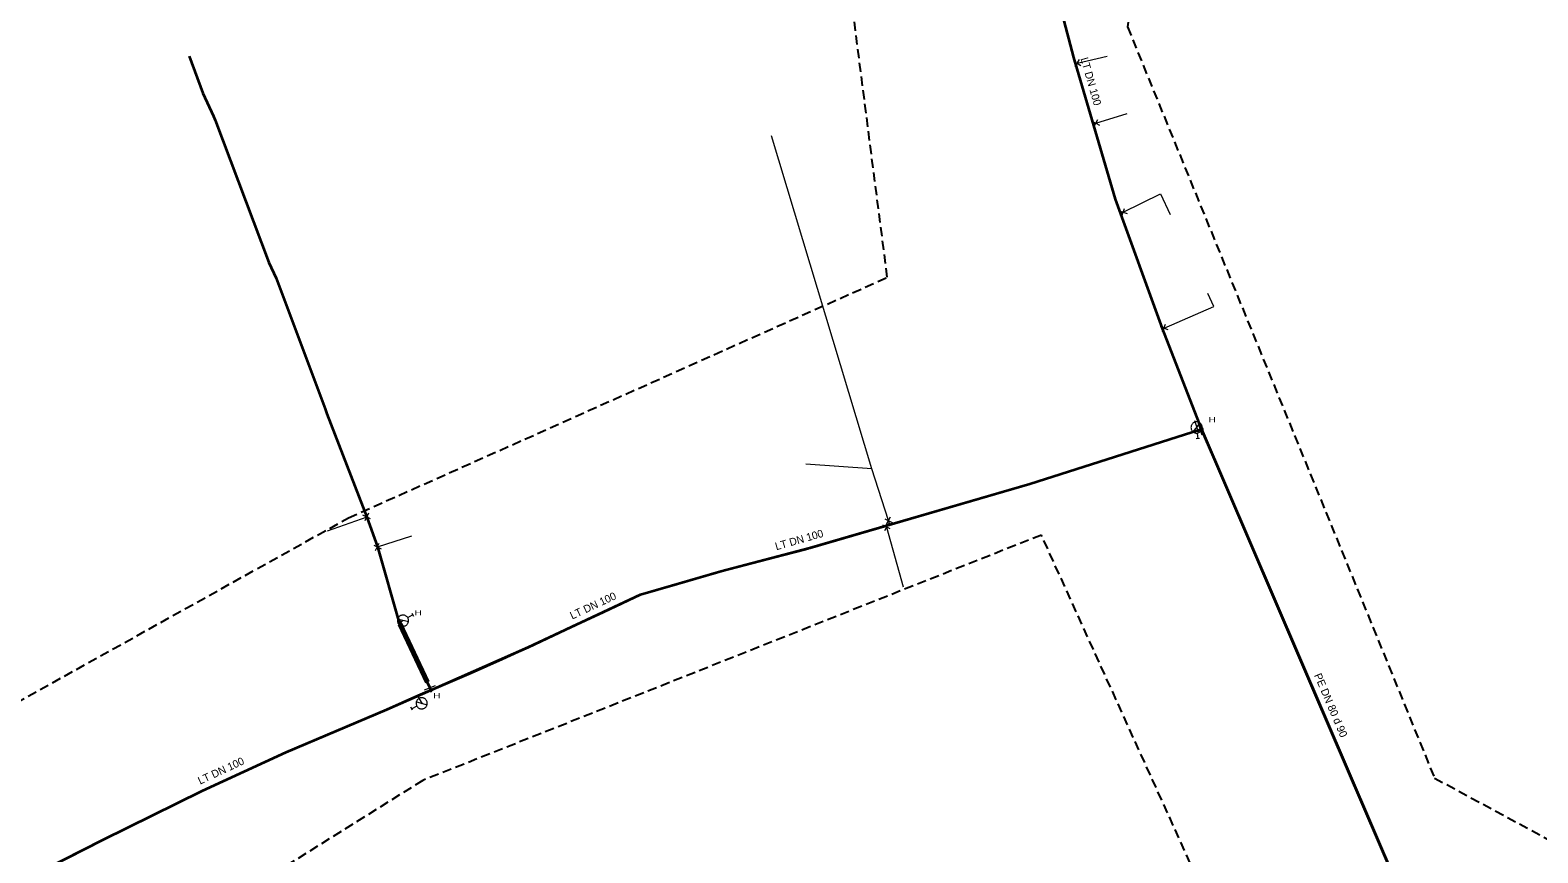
# Model space of a CAD drawing. Extents: x -743677 to -742923, y -1027084 to -1026416.
# Drawn here: x -743300.4 to -743064.4, y -1026690.3 to -1026561.5 of the extents above; entities that cross this region are included whole.
import ezdxf

# ---------------------------------------------------------------- set-up
doc = ezdxf.new("R2010")
doc.units = 0
doc.header["$LTSCALE"] = 0.48
doc.linetypes.add('MEDIUM_DASHED', pattern=[4.5, 3, -1.5])
for name, color, linetype, lineweight in [('15', 7, 'Continuous', 13), ('16', 7, 'Continuous', 35), ('20', 7, 'Continuous', 13), ('23', 7, 'Continuous', 70), ('59', 7, 'Continuous', 13), ('62', 7, 'MEDIUM_DASHED', 25)]:
    doc.layers.add(name, color=color, linetype=linetype, lineweight=lineweight)
doc.layers.add('17', color=7, linetype='Continuous')

msp = doc.modelspace()

# ---------------------------------------------------------------- linework, layer by layer
at = {"layer": '15'}
for p, q in [((-743137.057, -1026566.381), (-743135.96, -1026567.061)), ((-743136.85, -1026567.272), (-743136.167, -1026566.164)), ((-743134.177, -1026575.805), (-743133.041, -1026576.417)), ((-743133.916, -1026576.682), (-743133.301, -1026575.535)), ((-743129.919, -1026589.853), (-743128.698, -1026590.268)), ((-743129.517, -1026590.675), (-743129.101, -1026589.442)), ((-743123.518, -1026607.952), (-743122.319, -1026608.43)), ((-743123.159, -1026608.793), (-743122.679, -1026607.583)), ((-743118.136, -1026622.664), (-743117.563, -1026624.436)), ((-743116.971, -1026624.944), (-743117.548, -1026623.174)), ((-743247.117, -1026638.035), (-743248.283, -1026637.482)), ((-743247.422, -1026637.172), (-743247.978, -1026638.349)), ((-743166.615, -1026638.031), (-743165.462, -1026638.611)), ((-743166.33, -1026638.9), (-743165.747, -1026637.736)), ((-743165.777, -1026639.624), (-743166.924, -1026639.033)), ((-743166.053, -1026638.752), (-743166.647, -1026639.91)), ((-743246.601, -1026642.153), (-743245.456, -1026642.749)), ((-743246.328, -1026643.026), (-743245.729, -1026641.87)), ((-743241.867, -1026654.975), (-743242.832, -1026653.383)), ((-743238.664, -1026664.832), (-743236.934, -1026664.146))]:
    msp.add_line(p, q, dxfattribs=at)
for points in [[(-743116.803, -1026623.984), (-743116.809, -1026623.932), (-743116.826, -1026623.882), (-743116.855, -1026623.838), (-743116.892, -1026623.801), (-743116.937, -1026623.774), (-743116.987, -1026623.757), (-743117.04, -1026623.753), (-743117.092, -1026623.76), (-743117.141, -1026623.779), (-743117.184, -1026623.808), (-743117.22, -1026623.847), (-743117.246, -1026623.892), (-743117.262, -1026623.943), (-743117.265, -1026623.995), (-743117.257, -1026624.047), (-743117.237, -1026624.096), (-743117.206, -1026624.139), (-743117.167, -1026624.173), (-743117.121, -1026624.199), (-743117.07, -1026624.213), (-743117.017, -1026624.215), (-743116.966, -1026624.205), (-743116.918, -1026624.184), (-743116.875, -1026624.153), (-743116.841, -1026624.112), (-743116.817, -1026624.066), (-743116.804, -1026624.015)], [(-743116.833, -1026623.984), (-743116.839, -1026623.935), (-743116.856, -1026623.889), (-743116.884, -1026623.849), (-743116.921, -1026623.817), (-743116.965, -1026623.795), (-743117.013, -1026623.784), (-743117.062, -1026623.784), (-743117.108, -1026623.797), (-743117.152, -1026623.821), (-743117.188, -1026623.854), (-743117.215, -1026623.895), (-743117.231, -1026623.942), (-743117.235, -1026623.991), (-743117.228, -1026624.039), (-743117.209, -1026624.084), (-743117.179, -1026624.124), (-743117.141, -1026624.155), (-743117.097, -1026624.175), (-743117.049, -1026624.185), (-743117, -1026624.183), (-743116.953, -1026624.168), (-743116.91, -1026624.143), (-743116.875, -1026624.109), (-743116.85, -1026624.067), (-743116.836, -1026624.02)], [(-743116.863, -1026623.984), (-743116.869, -1026623.939), (-743116.886, -1026623.897), (-743116.914, -1026623.862), (-743116.95, -1026623.835), (-743116.992, -1026623.818), (-743117.037, -1026623.813), (-743117.081, -1026623.819), (-743117.123, -1026623.838), (-743117.157, -1026623.866), (-743117.184, -1026623.903), (-743117.201, -1026623.945), (-743117.205, -1026623.99), (-743117.198, -1026624.035), (-743117.179, -1026624.076), (-743117.15, -1026624.11), (-743117.113, -1026624.136), (-743117.07, -1026624.152), (-743117.025, -1026624.155), (-743116.98, -1026624.147), (-743116.94, -1026624.127), (-743116.906, -1026624.098), (-743116.88, -1026624.06), (-743116.866, -1026624.017)], [(-743116.893, -1026623.984), (-743116.897, -1026623.943), (-743116.916, -1026623.906), (-743116.943, -1026623.875), (-743116.978, -1026623.854), (-743117.018, -1026623.843), (-743117.059, -1026623.845), (-743117.098, -1026623.858), (-743117.132, -1026623.882), (-743117.157, -1026623.914), (-743117.172, -1026623.952), (-743117.174, -1026623.993), (-743117.167, -1026624.033), (-743117.147, -1026624.069), (-743117.118, -1026624.098), (-743117.081, -1026624.117), (-743117.041, -1026624.125), (-743117, -1026624.121), (-743116.962, -1026624.106), (-743116.929, -1026624.08), (-743116.907, -1026624.046), (-743116.894, -1026624.007)], [(-743116.923, -1026623.984), (-743116.928, -1026623.948), (-743116.946, -1026623.916), (-743116.972, -1026623.891), (-743117.005, -1026623.876), (-743117.042, -1026623.873), (-743117.076, -1026623.881), (-743117.108, -1026623.901), (-743117.13, -1026623.929), (-743117.144, -1026623.963), (-743117.144, -1026624), (-743117.133, -1026624.035), (-743117.112, -1026624.064), (-743117.081, -1026624.085), (-743117.047, -1026624.095), (-743117.01, -1026624.093), (-743116.976, -1026624.079), (-743116.949, -1026624.056), (-743116.929, -1026624.024), (-743116.923, -1026623.989)], [(-743116.953, -1026623.984), (-743116.958, -1026623.953), (-743116.975, -1026623.927), (-743117, -1026623.91), (-743117.031, -1026623.903), (-743117.062, -1026623.907), (-743117.089, -1026623.924), (-743117.107, -1026623.948), (-743117.115, -1026623.979), (-743117.111, -1026624.009), (-743117.096, -1026624.037), (-743117.071, -1026624.056), (-743117.042, -1026624.065), (-743117.011, -1026624.062), (-743116.983, -1026624.048), (-743116.963, -1026624.024), (-743116.953, -1026623.995)], [(-743116.983, -1026623.984), (-743116.988, -1026623.96), (-743117.005, -1026623.942), (-743117.027, -1026623.933), (-743117.052, -1026623.936), (-743117.073, -1026623.95), (-743117.084, -1026623.972), (-743117.084, -1026623.997), (-743117.071, -1026624.018), (-743117.052, -1026624.032), (-743117.027, -1026624.035), (-743117.004, -1026624.026), (-743116.988, -1026624.008)], [(-743117.013, -1026623.984), (-743117.018, -1026623.969), (-743117.032, -1026623.963), (-743117.048, -1026623.967), (-743117.054, -1026623.981), (-743117.051, -1026623.996), (-743117.038, -1026624.005), (-743117.022, -1026624.002), (-743117.013, -1026623.99)], [(-743237.449, -1026664.856), (-743237.455, -1026664.804), (-743237.472, -1026664.754), (-743237.501, -1026664.71), (-743237.538, -1026664.673), (-743237.583, -1026664.646), (-743237.633, -1026664.629), (-743237.686, -1026664.625), (-743237.738, -1026664.632), (-743237.787, -1026664.651), (-743237.83, -1026664.68), (-743237.866, -1026664.719), (-743237.892, -1026664.764), (-743237.908, -1026664.815), (-743237.911, -1026664.867), (-743237.903, -1026664.919), (-743237.883, -1026664.968), (-743237.852, -1026665.011), (-743237.813, -1026665.045), (-743237.767, -1026665.071), (-743237.716, -1026665.085), (-743237.663, -1026665.087), (-743237.612, -1026665.077), (-743237.564, -1026665.056), (-743237.521, -1026665.025), (-743237.487, -1026664.984), (-743237.463, -1026664.938), (-743237.451, -1026664.887)], [(-743237.479, -1026664.856), (-743237.485, -1026664.807), (-743237.502, -1026664.761), (-743237.53, -1026664.721), (-743237.567, -1026664.689), (-743237.611, -1026664.667), (-743237.659, -1026664.656), (-743237.708, -1026664.656), (-743237.755, -1026664.669), (-743237.798, -1026664.693), (-743237.834, -1026664.726), (-743237.861, -1026664.767), (-743237.877, -1026664.814), (-743237.881, -1026664.863), (-743237.874, -1026664.911), (-743237.855, -1026664.956), (-743237.825, -1026664.996), (-743237.787, -1026665.027), (-743237.743, -1026665.047), (-743237.695, -1026665.057), (-743237.646, -1026665.055), (-743237.599, -1026665.04), (-743237.556, -1026665.015), (-743237.522, -1026664.981), (-743237.496, -1026664.939), (-743237.482, -1026664.892)], [(-743237.509, -1026664.856), (-743237.515, -1026664.811), (-743237.532, -1026664.769), (-743237.56, -1026664.734), (-743237.596, -1026664.707), (-743237.638, -1026664.69), (-743237.683, -1026664.685), (-743237.728, -1026664.691), (-743237.769, -1026664.71), (-743237.804, -1026664.738), (-743237.831, -1026664.775), (-743237.847, -1026664.817), (-743237.851, -1026664.862), (-743237.844, -1026664.907), (-743237.825, -1026664.948), (-743237.796, -1026664.982), (-743237.759, -1026665.008), (-743237.716, -1026665.024), (-743237.671, -1026665.027), (-743237.626, -1026665.019), (-743237.586, -1026664.999), (-743237.552, -1026664.97), (-743237.526, -1026664.932), (-743237.512, -1026664.889)], [(-743237.539, -1026664.856), (-743237.544, -1026664.815), (-743237.562, -1026664.778), (-743237.589, -1026664.747), (-743237.624, -1026664.726), (-743237.664, -1026664.715), (-743237.705, -1026664.717), (-743237.744, -1026664.73), (-743237.778, -1026664.754), (-743237.803, -1026664.786), (-743237.818, -1026664.824), (-743237.821, -1026664.865), (-743237.813, -1026664.905), (-743237.793, -1026664.941), (-743237.764, -1026664.97), (-743237.727, -1026664.989), (-743237.687, -1026664.997), (-743237.646, -1026664.993), (-743237.608, -1026664.978), (-743237.576, -1026664.952), (-743237.553, -1026664.918), (-743237.54, -1026664.879)], [(-743237.569, -1026664.856), (-743237.574, -1026664.82), (-743237.592, -1026664.788), (-743237.618, -1026664.763), (-743237.652, -1026664.748), (-743237.688, -1026664.745), (-743237.723, -1026664.753), (-743237.754, -1026664.773), (-743237.777, -1026664.801), (-743237.79, -1026664.835), (-743237.79, -1026664.872), (-743237.779, -1026664.907), (-743237.758, -1026664.936), (-743237.728, -1026664.957), (-743237.693, -1026664.967), (-743237.656, -1026664.965), (-743237.622, -1026664.951), (-743237.595, -1026664.928), (-743237.576, -1026664.896), (-743237.569, -1026664.861)], [(-743237.599, -1026664.856), (-743237.604, -1026664.825), (-743237.621, -1026664.799), (-743237.647, -1026664.782), (-743237.677, -1026664.775), (-743237.708, -1026664.779), (-743237.735, -1026664.796), (-743237.753, -1026664.82), (-743237.761, -1026664.851), (-743237.757, -1026664.881), (-743237.742, -1026664.909), (-743237.718, -1026664.928), (-743237.688, -1026664.937), (-743237.657, -1026664.934), (-743237.629, -1026664.92), (-743237.609, -1026664.896), (-743237.599, -1026664.867)], [(-743237.629, -1026664.856), (-743237.634, -1026664.832), (-743237.651, -1026664.814), (-743237.674, -1026664.805), (-743237.698, -1026664.808), (-743237.719, -1026664.822), (-743237.73, -1026664.844), (-743237.73, -1026664.869), (-743237.718, -1026664.89), (-743237.698, -1026664.904), (-743237.673, -1026664.907), (-743237.65, -1026664.898), (-743237.634, -1026664.88)], [(-743237.659, -1026664.856), (-743237.664, -1026664.841), (-743237.679, -1026664.835), (-743237.694, -1026664.839), (-743237.701, -1026664.853), (-743237.697, -1026664.868), (-743237.684, -1026664.877), (-743237.669, -1026664.874), (-743237.659, -1026664.862)]]:
    msp.add_lwpolyline(points, close=True, dxfattribs=at)
at = {"layer": '16'}
for p, q in [((-743117.26, -1026624.059), (-743117.034, -1026623.984)), ((-743237.8, -1026664.489), (-743237.681, -1026664.856))]:
    msp.add_line(p, q, dxfattribs=at)
for points in [[(-743117.034, -1026623.984), (-743117.054, -1026623.936), (-743123.186, -1026608.25), (-743130.522, -1026587.991), (-743137.061, -1026565.84), (-743149.689, -1026517.647)], [(-743275.469, -1026565.629), (-743273.333, -1026571.386), (-743271.649, -1026575.03), (-743271.423, -1026575.629), (-743263.019, -1026597.92), (-743261.87, -1026600.39), (-743254.21, -1026620.85), (-743253.96, -1026621.6), (-743247.699, -1026637.76), (-743246.03, -1026642.449), (-743242.6, -1026654.329), (-743237.8, -1026664.489)], [(-743298.416, -1026693.105), (-743288.989, -1026688.28), (-743273.469, -1026680.6), (-743260.32, -1026674.559), (-743244.57, -1026667.879), (-743239.641, -1026665.717), (-743238.161, -1026665.067), (-743237.938, -1026664.969), (-743237.577, -1026664.811), (-743231.373, -1026662.127), (-743226.444, -1026659.975), (-743223.96, -1026658.835), (-743222.396, -1026658.148), (-743215.519, -1026654.916), (-743210.612, -1026652.609), (-743204.853, -1026649.905), (-743199.059, -1026648.225), (-743192.97, -1026646.46), (-743192.086, -1026646.208), (-743182.459, -1026643.677), (-743179.047, -1026642.78), (-743178.648, -1026642.675), (-743178.396, -1026642.609), (-743178.3, -1026642.581), (-743143.91, -1026632.55), (-743117.26, -1026624.059)], [(-743237.681, -1026664.856), (-743222.42, -1026658.16), (-743204.87, -1026649.91), (-743192.28, -1026646.26), (-743178.399, -1026642.609), (-743143.91, -1026632.55), (-743117.26, -1026624.059), (-743117.034, -1026623.984)], [(-743070.292, -1026711.107), (-743071.72, -1026710.014), (-743073.722, -1026708.481), (-743078.157, -1026705.085), (-743085.529, -1026696.263), (-743086.594, -1026694.989), (-743099.513, -1026664.855), (-743110.476, -1026639.282), (-743115.012, -1026628.701), (-743117.034, -1026623.984)], [(-743117.034, -1026623.984), (-743086.594, -1026694.989), (-743078.157, -1026705.085), (-743072.203, -1026709.645), (-743070.292, -1026711.107)], [(-743298.535, -1026693.171), (-743298.402, -1026693.098), (-743298.142, -1026692.965), (-743297.201, -1026692.483), (-743288.989, -1026688.28), (-743273.469, -1026680.6), (-743260.32, -1026674.559), (-743244.57, -1026667.879), (-743237.681, -1026664.856)]]:
    msp.add_lwpolyline(points, dxfattribs=at)
at = {"layer": '20'}
for p, q in [((-743118.375, -1026624.422), (-743117.272, -1026623.063)), ((-743117.372, -1026625.475), (-743117.91, -1026625.531)), ((-743117.731, -1026624.624), (-743117.64, -1026625.503)), ((-743241.173, -1026654.183), (-743242.873, -1026653.767)), ((-743241.265, -1026653.515), (-743240.509, -1026653.057)), ((-743240.649, -1026652.826), (-743240.369, -1026653.289)), ((-743240.512, -1026668.008), (-743240.77, -1026667.533)), ((-743239.863, -1026667.35), (-743240.64, -1026667.771)), ((-743239.923, -1026666.678), (-743238.246, -1026667.176))]:
    msp.add_line(p, q, dxfattribs=at)
for points in [[(-743118.698, -1026623.834), (-743118.685, -1026623.923), (-743118.661, -1026624.011), (-743118.628, -1026624.098), (-743118.588, -1026624.178), (-743118.538, -1026624.256), (-743118.48, -1026624.328), (-743118.415, -1026624.392), (-743118.344, -1026624.451), (-743118.267, -1026624.499), (-743118.186, -1026624.541), (-743118.1, -1026624.574), (-743118.011, -1026624.599), (-743117.921, -1026624.614), (-743117.83, -1026624.619), (-743117.739, -1026624.613), (-743117.647, -1026624.6), (-743117.559, -1026624.577), (-743117.474, -1026624.544), (-743117.392, -1026624.501), (-743117.315, -1026624.451), (-743117.245, -1026624.393), (-743117.179, -1026624.33), (-743117.122, -1026624.258), (-743117.071, -1026624.182), (-743117.03, -1026624.1), (-743116.996, -1026624.014), (-743116.973, -1026623.927), (-743116.958, -1026623.835), (-743116.954, -1026623.744), (-743116.957, -1026623.652), (-743116.973, -1026623.563), (-743116.996, -1026623.475), (-743117.029, -1026623.388), (-743117.069, -1026623.308), (-743117.12, -1026623.23), (-743117.177, -1026623.158), (-743117.242, -1026623.094), (-743117.313, -1026623.035), (-743117.39, -1026622.987), (-743117.471, -1026622.945), (-743117.557, -1026622.912), (-743117.646, -1026622.887), (-743117.735, -1026622.874), (-743117.827, -1026622.867), (-743117.919, -1026622.873), (-743118.01, -1026622.886), (-743118.098, -1026622.911), (-743118.183, -1026622.942), (-743118.265, -1026622.985), (-743118.342, -1026623.035), (-743118.413, -1026623.093), (-743118.478, -1026623.156), (-743118.535, -1026623.228), (-743118.586, -1026623.304), (-743118.627, -1026623.386), (-743118.661, -1026623.472), (-743118.684, -1026623.559), (-743118.699, -1026623.651), (-743118.703, -1026623.742), (-743118.698, -1026623.832)], [(-743241.566, -1026654.727), (-743241.491, -1026654.677), (-743241.421, -1026654.618), (-743241.357, -1026654.551), (-743241.302, -1026654.48), (-743241.253, -1026654.402), (-743241.213, -1026654.318), (-743241.183, -1026654.232), (-743241.159, -1026654.143), (-743241.149, -1026654.053), (-743241.146, -1026653.962), (-743241.152, -1026653.87), (-743241.168, -1026653.779), (-743241.193, -1026653.691), (-743241.227, -1026653.607), (-743241.272, -1026653.526), (-743241.323, -1026653.45), (-743241.381, -1026653.38), (-743241.447, -1026653.317), (-743241.521, -1026653.261), (-743241.6, -1026653.213), (-743241.682, -1026653.174), (-743241.767, -1026653.141), (-743241.857, -1026653.121), (-743241.946, -1026653.107), (-743242.039, -1026653.105), (-743242.131, -1026653.112), (-743242.219, -1026653.128), (-743242.309, -1026653.154), (-743242.393, -1026653.189), (-743242.475, -1026653.231), (-743242.549, -1026653.283), (-743242.618, -1026653.342), (-743242.683, -1026653.409), (-743242.738, -1026653.48), (-743242.787, -1026653.558), (-743242.827, -1026653.641), (-743242.857, -1026653.727), (-743242.88, -1026653.816), (-743242.891, -1026653.907), (-743242.894, -1026653.998), (-743242.888, -1026654.089), (-743242.872, -1026654.181), (-743242.845, -1026654.267), (-743242.812, -1026654.353), (-743242.768, -1026654.433), (-743242.717, -1026654.51), (-743242.657, -1026654.579), (-743242.592, -1026654.642), (-743242.519, -1026654.698), (-743242.44, -1026654.747), (-743242.358, -1026654.786), (-743242.273, -1026654.818), (-743242.183, -1026654.839), (-743242.093, -1026654.852), (-743242.001, -1026654.854), (-743241.909, -1026654.848), (-743241.82, -1026654.832), (-743241.731, -1026654.806), (-743241.647, -1026654.771), (-743241.568, -1026654.728)], [(-743239.504, -1026666.154), (-743239.582, -1026666.201), (-743239.654, -1026666.256), (-743239.722, -1026666.32), (-743239.78, -1026666.388), (-743239.832, -1026666.464), (-743239.877, -1026666.545), (-743239.911, -1026666.629), (-743239.939, -1026666.717), (-743239.954, -1026666.807), (-743239.961, -1026666.898), (-743239.959, -1026666.99), (-743239.948, -1026667.082), (-743239.927, -1026667.171), (-743239.897, -1026667.256), (-743239.856, -1026667.339), (-743239.809, -1026667.418), (-743239.754, -1026667.491), (-743239.691, -1026667.556), (-743239.62, -1026667.616), (-743239.544, -1026667.668), (-743239.464, -1026667.711), (-743239.38, -1026667.748), (-743239.292, -1026667.772), (-743239.203, -1026667.79), (-743239.11, -1026667.797), (-743239.018, -1026667.795), (-743238.929, -1026667.783), (-743238.838, -1026667.761), (-743238.753, -1026667.731), (-743238.669, -1026667.692), (-743238.593, -1026667.644), (-743238.52, -1026667.589), (-743238.452, -1026667.525), (-743238.394, -1026667.457), (-743238.342, -1026667.381), (-743238.297, -1026667.299), (-743238.263, -1026667.215), (-743238.236, -1026667.127), (-743238.221, -1026667.037), (-743238.213, -1026666.947), (-743238.215, -1026666.855), (-743238.226, -1026666.763), (-743238.249, -1026666.675), (-743238.277, -1026666.588), (-743238.318, -1026666.505), (-743238.365, -1026666.426), (-743238.422, -1026666.355), (-743238.483, -1026666.288), (-743238.554, -1026666.229), (-743238.63, -1026666.177), (-743238.71, -1026666.134), (-743238.794, -1026666.097), (-743238.882, -1026666.072), (-743238.972, -1026666.054), (-743239.064, -1026666.048), (-743239.156, -1026666.05), (-743239.245, -1026666.062), (-743239.336, -1026666.083), (-743239.422, -1026666.114), (-743239.503, -1026666.153)]]:
    msp.add_lwpolyline(points, dxfattribs=at)
at = {"layer": '23'}
msp.add_line((-743242.496, -1026654.548), (-743238.226, -1026663.588), dxfattribs=at)
at = {"layer": '59'}
for p, q in [((-743168.656, -1026630.202), (-743184.338, -1026578.079)), ((-743168.656, -1026630.202), (-743184.338, -1026578.079)), ((-743247.699, -1026637.76), (-743253.899, -1026639.989)), ((-743246.03, -1026642.449), (-743240.62, -1026640.73)), ((-743239.727, -1026665.754), (-743239.03, -1026667.03)), ((-743239.718, -1026665.75), (-743239.088, -1026666.923))]:
    msp.add_line(p, q, dxfattribs=at)
for points in [[(-743136.78, -1026566.792), (-743136.51, -1026566.72), (-743131.815, -1026565.603)], [(-743133.998, -1026576.216), (-743133.61, -1026576.11), (-743128.677, -1026574.616)], [(-743129.716, -1026590.216), (-743129.31, -1026590.06), (-743123.483, -1026587.172), (-743121.988, -1026590.4)], [(-743123.173, -1026608.282), (-743122.92, -1026608.19), (-743115.151, -1026604.828), (-743116.082, -1026602.771)], [(-743117.278, -1026623.365), (-743117.85, -1026623.55), (-743117.829, -1026623.744)], [(-743165.831, -1026638.944), (-743166.04, -1026638.32), (-743168.656, -1026630.202), (-743178.959, -1026629.463)], [(-743165.832, -1026638.944), (-743166.04, -1026638.32), (-743168.656, -1026630.202), (-743178.959, -1026629.463)], [(-743166.427, -1026639.092), (-743166.35, -1026639.33), (-743163.739, -1026648.691)], [(-743166.419, -1026639.115), (-743166.35, -1026639.33), (-743163.739, -1026648.691)], [(-743242.6, -1026654.33), (-743242.35, -1026654.18), (-743242.02, -1026653.98)]]:
    msp.add_lwpolyline(points, dxfattribs=at)
at = {"layer": '62'}
msp.add_lwpolyline([(-743185.331, -1026452.124), (-743185.314, -1026452.115), (-743122.624, -1026517.483), (-743128.636, -1026561.04), (-743080.591, -1026678.626), (-742988.56, -1026728.316), (-742957.099, -1026715.401), (-742922.946, -1026754.658), (-742988.389, -1026762.896), (-743109.886, -1026711.598), (-743142.114, -1026640.576), (-743238.891, -1026678.985), (-743355.253, -1026751.681), (-743402.763, -1026809.228), (-743453.197, -1026905.826), (-743482.789, -1027084.226), (-743535.862, -1027074.436), (-743492.719, -1026905.289), (-743434.421, -1026787.581), (-743381.806, -1026711.007), (-743250.543, -1026637.895), (-743166.228, -1026600.23)], close=True, dxfattribs=at)

# ---------------------------------------------------------------- texts
at = {"layer": '17'}
for s, rotation, p in [('LT DN 100 ', 286, (-743136.003, -1026565.999)), ('LT DN 100 ', 16, (-743183.591, -1026642.971)), ('LT DN 100 ', 25, (-743215.543, -1026653.817)), ('PE DN 80 d 90 ', 293, (-743099.459, -1026662.525)), ('PE DN 80 d 90 ', 293, (-743099.459, -1026662.531)), ('LT DN 100 ', 25, (-743273.765, -1026679.662))]:
    msp.add_text(s, height=1.2, rotation=rotation, dxfattribs=at).set_placement(p)
at = {"layer": '20', "width": 1.45}
for p in [(-743115.952, -1026622.914), (-743240.198, -1026653.175), (-743237.269, -1026666.119)]:
    msp.add_text('H ', height=0.8, dxfattribs=at).set_placement(p)

doc.saveas('drawing.dxf')
